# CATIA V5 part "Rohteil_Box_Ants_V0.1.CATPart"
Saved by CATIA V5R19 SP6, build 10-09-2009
Part number: Rohteil_Box_Ants_V0.1
Publications: "Mehrfachableitung.2"
Bounding box of the stored display mesh (mm): x -746.9 to 1.9, y 0 to 316.072, z -2 to 30
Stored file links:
  C:\Dokumente und Einstellungen\ants\Desktop\Rohteil_Box_Ants_V0.1.CATPart
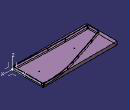
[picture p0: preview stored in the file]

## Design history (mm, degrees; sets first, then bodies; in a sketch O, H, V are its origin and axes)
Parameters
  Rohteil = ""
  LENGTH = 748.8001 mm {= Sketch1.length(L2)}
  Breite = 308.3393 mm {= Sketch1.length(L1)}
  `Höhe` = 32 mm
AxisSystem1: origin (0, 0, 0), X (1, 0, 0), Y (0, 1, 0), Z (0, 0, 1)
Set1 "Veröffendlichung"
  MultiExtract1: ListOfMultiExtractConstraints MultiExtractConstraint Body2
Set2 "Rohteil"
  MultiExtract2: ListOfMultiExtractConstraints MultiExtractConstraint Body2
  Extremum1: Reference MultiExtract2, Direction Line2, Direction2 (0, 0, 1), Direction3 (0, 0, 1)
  Extremum2: Reference MultiExtract2, Direction Line2, Direction2 (0, 0, 1), Direction3 (0, 0, 1)
  Plane1: type Offset, RefPlane Extremum1, Offset 0
  Line1: type PtPt, FirstPoint vertex [face of Extremum1], SecondPoint vertex [face of Extremum1]
  Boundary1: Boundary edge of Extremum1
  Sketch1 on Plane1, origin (0, 0, 30), H (0, 1, 0), V (-1, 0, 0)
    reference projected curve E1 from Boundary1
    line L1 (7.0021, 746.9) -> (315.3414, 746.9001)
    line L2 (315.3414, 746.9001) -> (315.3414, -1.9)
    line L3 (315.3414, -1.9) -> (7.0021, -1.9)
    line L4 (7.0021, -1.9) -> (7.0021, 746.9)
    length L2 = 748.8001 (reference)
    length L1 = 308.3393 (reference)
    tangency: L3 E1, L4 E1, L1 E1, L2 E1
  Extract1: ExtractElem face of Extremum2
  Plane2: type Offset, RefPlane Extract1, Offset 0
  Line2: stored without definition
  Extrude1: Element1 Sketch1, Lim1 0, Lim2 0, FirstUpto Plane2
Body1 (main body)
Body2 "RIB-MAIN 03"
  Solid1: solid without history
  Thickness1: Thickness 2, Face face of Solid1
